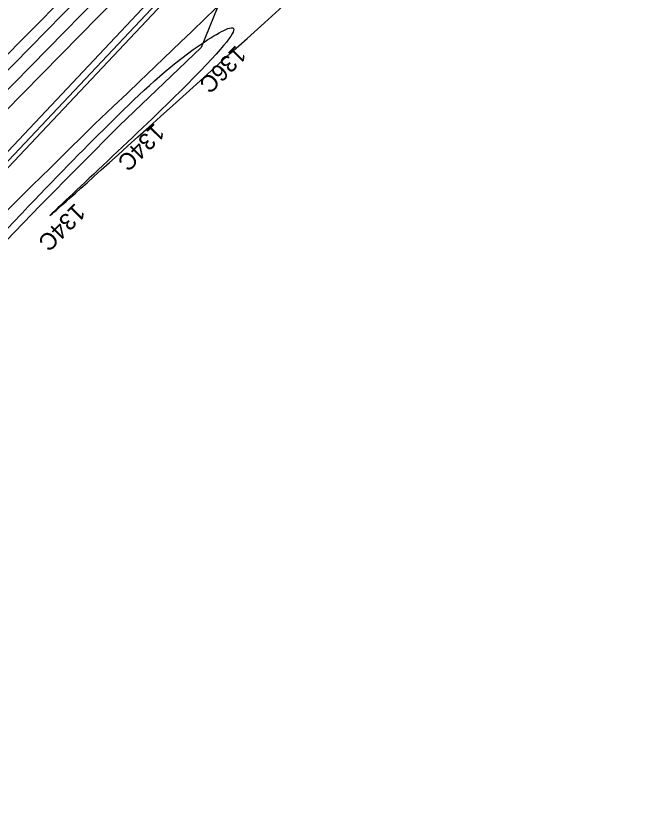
# Model space of a CAD drawing. Extents: x 2163396 to 2173129, y 605545 to 614595.
# Drawn here: x 2164110 to 2164654, y 605580 to 606275 of the extents above; entities that cross this region are included whole.
import ezdxf

# ---------------------------------------------------------------- set-up
doc = ezdxf.new("R2010")
doc.units = 0
for name, color, linetype in [('RD_PD_AsphRem', 7, 'Continuous'), ('RD_PD_CstnLmt', 7, 'Continuous'), ('RD_PD_DR_Ditch', 7, 'Continuous'), ('RD_PD_EarthShd', 7, 'Continuous'), ('RD_PD_Final_LnLine', 7, 'Continuous'), ('RD_PD_Final_TrvlWay', 7, 'Continuous'), ('RD_PD_TX_CstnLmt', 7, 'Continuous')]:
    doc.layers.add(name, color=color, linetype=linetype)

msp = doc.modelspace()

# ---------------------------------------------------------------- linework, layer by layer
at = {"layer": 'RD_PD_AsphRem'}
msp.add_line((2164359.8, 606418.62), (2164041.5, 606080.93), dxfattribs=at)
msp.add_lwpolyline([(2164095.12, 606095.5), (2164109.89, 606109.86), (2164124.53, 606124.36), (2164140.42, 606139.8), (2164155.9, 606155.29), (2164170.6, 606169.74), (2164179.88, 606178.98), (2164196.73, 606194.82), (2164208.71, 606206.11), (2164220, 606216.98), (2164226.29, 606222.97), (2164240.94, 606237.07), (2164256.34, 606251.93), (2164265.79, 606260.84), (2164278.71, 606273.04), (2164293.4, 606287.25)], dxfattribs=at)
at = {"layer": 'RD_PD_CstnLmt'}
for p, q in [((2164315.12, 606347.56), (2164274.49, 606246.84)), ((2164274.49, 606246.84), (2164202.08, 606177.82)), ((2164202.08, 606177.82), (2164131.69, 606106.79)), ((2164131.69, 606106.79), (2164062.14, 606034.93))]:
    msp.add_line(p, q, dxfattribs=at)
at = {"layer": 'RD_PD_DR_Ditch'}
msp.add_open_spline([(2163992.13, 605963.52), (2164058.06, 606038.99), (2164126.34, 606112.13), (2164196.48, 606183.41), (2164268.87, 606252.45), (2164363.94, 606298.86), (2163992.13, 605963.52), (2164363.94, 606298.86)], degree=3, dxfattribs=at)
at = {"layer": 'RD_PD_EarthShd'}
msp.add_line((2164044.41, 606078.18), (2164654.42, 606725.37), dxfattribs=at)
at = {"layer": 'RD_PD_Final_LnLine'}
for p, q in [((2164619.71, 606753.17), (2163476.13, 605588.59)), ((2164628.27, 606744.76), (2163484.63, 605580.12)), ((2164636.77, 606736.29), (2164100.27, 606189.93)), ((2164037.13, 606085.04), (2164644.06, 606729.01))]:
    msp.add_line(p, q, dxfattribs=at)
at = {"layer": 'RD_PD_Final_TrvlWay'}
for p, q in [((2164612.69, 606760.3), (2163889.38, 606023.71)), ((2164041.5, 606080.93), (2164648.31, 606724.77))]:
    msp.add_line(p, q, dxfattribs=at)

# ---------------------------------------------------------------- texts
at = {"layer": 'RD_PD_TX_CstnLmt'}
for s, p in [('136C', (2164305.45, 606249.56)), ('134C', (2164233.04, 606180.54)), ('134C', (2164162.65, 606109.51))]:
    msp.add_text(s, height=15, rotation=225.07107, dxfattribs=at).set_placement(p)

doc.saveas('drawing.dxf')
